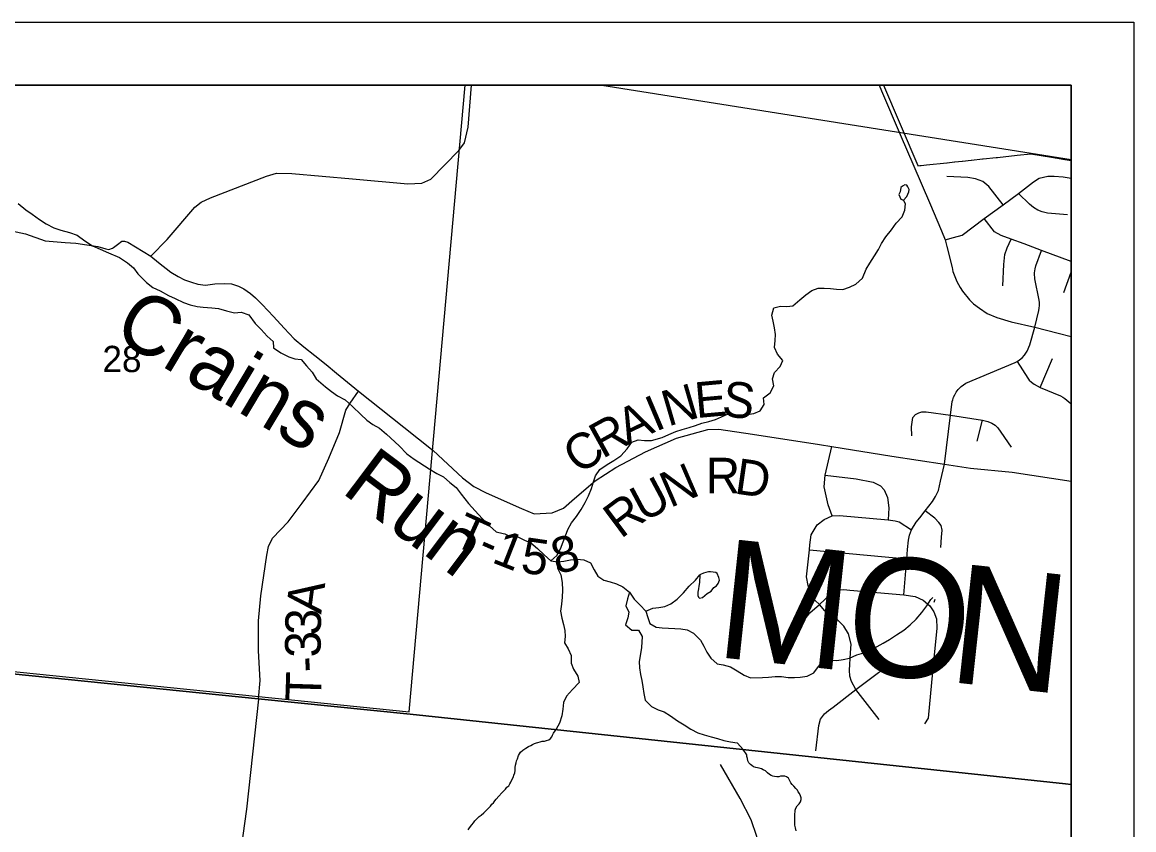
# Model space of a CAD drawing. Extents: x -7.3 to 34, y 0 to 22.
# Drawn here: x 7.229 to 9, y 19.714 to 21 of the extents above; entities that cross this region are included whole.
import ezdxf

# ---------------------------------------------------------------- set-up
doc = ezdxf.new("R2010")
doc.units = 0
for name, color, linetype in [('GM_X_Corporation', 7, 'Continuous'), ('GM_X_County_Road', 7, 'Continuous'), ('GM_X_County_Text', 7, 'Continuous'), ('GM_X_Minor_Lake', 7, 'Continuous'), ('GM_X_Minor_River', 7, 'Continuous'), ('GM_X_Minor_River_Text', 7, 'Continuous'), ('GM_X_Section_Text', 7, 'Continuous'), ('GM_X_Township_Road', 7, 'Continuous'), ('GM_X_Township_Road_Text', 7, 'Continuous'), ('SH_Data', 7, 'Continuous')]:
    doc.layers.add(name, color=color, linetype=linetype)

msp = doc.modelspace()

# ---------------------------------------------------------------- linework, layer by layer
at = {"layer": 'GM_X_Corporation'}
for points in [[(2.7422, 20.0783), (4.2288, 20.048), (4.2328, 20.0479), (4.4762, 20.0428), (4.7954, 20.036), (4.9235, 20.0334), (4.9401, 20.0331), (4.9519, 20.0328), (5.8024, 20.0153), (5.9388, 20.0125), (6.0214, 20.0108), (6.0677, 20.0098), (6.0763, 20.0096), (6.4154, 20.0027), (6.4242, 20.0024), (6.9507, 19.9888), (6.9988, 19.9839), (7.6051, 19.9224), (7.8469, 19.8978), (8.8913, 19.7872), (8.9, 19.7858), (8.9, 20.9), (2.1, 20.9)], [(6.9988, 19.9839), (7.6051, 19.9224), (7.8469, 19.8978), (8.8913, 19.7872), (8.9, 19.7858), (8.9, 20.9), (4.7796, 20.9)], [(8.9, 14.1), (8.9, 19.7858), (8.8913, 19.7872), (7.8469, 19.8978), (7.6051, 19.9224), (6.9988, 19.9839), (6.9507, 19.9888), (6.4242, 20.0024), (6.4154, 20.0027), (6.0763, 20.0096), (6.0677, 20.0098), (6.0214, 20.0108), (5.9388, 20.0125), (5.8024, 20.0153), (4.9519, 20.0328), (4.9401, 20.0331), (4.9235, 20.0334), (4.7954, 20.036), (4.4762, 20.0428), (4.2328, 20.0479), (4.2288, 20.048), (2.7422, 20.0783)], [(8.9, 19.3924), (8.9, 19.7858), (8.8913, 19.7872), (7.8469, 19.8978), (7.6051, 19.9224), (6.9988, 19.9839), (6.9507, 19.9888), (6.4242, 20.0024), (6.4154, 20.0027), (6.0763, 20.0096), (6.0677, 20.0098), (6.0214, 20.0108), (5.9388, 20.0125), (5.8024, 20.0153), (4.9519, 20.0328), (4.9401, 20.0331), (4.9235, 20.0334), (4.7954, 20.036), (4.4762, 20.0428), (4.2328, 20.0479), (4.2288, 20.048), (2.7422, 20.0783)]]:
    msp.add_lwpolyline(points, dxfattribs=at)
for points in [[(7.9348, 20.9), (6.9581, 20.9), (6.9466, 20.8915), (6.9213, 20.878), (6.9137, 20.8592), (6.868, 20.2988), (6.8838, 20.2576), (6.9047, 20.2424), (6.9439, 20.2121), (6.9658, 20.1923), (6.9852, 20.1575), (7.0057, 20.1052), (7.0065, 20.0839), (7.0034, 20.0639), (6.9909, 20.0255), (6.98, 19.9897), (7.8452, 19.9016)], [(8.9, 20.7813), (8.9, 20.9), (8.1523, 20.9)], [(8.9, 20.7798), (8.9, 20.9), (8.6014, 20.9), (8.6559, 20.7719), (8.6561, 20.7713), (8.659, 20.7717), (8.6597, 20.7717), (8.6609, 20.7719), (8.6612, 20.7719), (8.6695, 20.7728), (8.7023, 20.7763), (8.7028, 20.7763), (8.7146, 20.7776), (8.715, 20.7776), (8.7268, 20.7789), (8.7273, 20.7789), (8.7411, 20.7804), (8.7416, 20.7804), (8.7591, 20.7823), (8.7598, 20.7824), (8.7805, 20.7845), (8.7822, 20.7847), (8.783, 20.7848), (8.814, 20.7881), (8.8358, 20.7904), (8.8689, 20.785), (8.8748, 20.784), (8.8754, 20.7839), (8.8902, 20.7815), (8.8908, 20.7814)]]:
    msp.add_lwpolyline(points, close=True, dxfattribs=at)
at = {"layer": 'GM_X_County_Road'}
for points in [[(8.5943, 20.9), (8.5983, 20.8905), (8.6278, 20.8212), (8.6496, 20.7709), (8.6744, 20.7129), (8.6938, 20.668), (8.6997, 20.6534), (8.7022, 20.6428), (8.7104, 20.6092), (8.7117, 20.6029), (8.7183, 20.587), (8.7236, 20.5777)], [(8.7236, 20.5777), (8.727, 20.5718), (8.7385, 20.558), (8.7447, 20.5518), (8.7542, 20.5445), (8.7666, 20.5361), (8.782, 20.5297), (8.8048, 20.523), (8.8421, 20.5142), (8.8794, 20.5048), (8.9, 20.4997)]]:
    msp.add_lwpolyline(points, dxfattribs=at)
at = {"layer": 'GM_X_Minor_Lake'}
for points in [[(8.6332, 20.7167), (8.6382, 20.7227), (8.6418, 20.7298), (8.6423, 20.7336), (8.6401, 20.7378), (8.6386, 20.7405), (8.6352, 20.741), (8.6313, 20.7391), (8.629, 20.7369)], [(8.629, 20.7369), (8.6277, 20.7297), (8.6258, 20.7259), (8.6287, 20.7183), (8.6332, 20.7167)], [(8.3085, 20.12), (8.3083, 20.1077)], [(8.3388, 20.1155), (8.3363, 20.122), (8.334, 20.1239), (8.3298, 20.1244), (8.3257, 20.1248), (8.3222, 20.1245), (8.3184, 20.1235), (8.3142, 20.1228), (8.3096, 20.1206), (8.3085, 20.12)], [(8.3083, 20.1077), (8.307, 20.102), (8.3065, 20.0978), (8.3053, 20.0925), (8.3052, 20.0869), (8.3063, 20.0846), (8.3082, 20.083), (8.3127, 20.0837), (8.3201, 20.0904), (8.3266, 20.0937), (8.3309, 20.0997), (8.3351, 20.1026), (8.3378, 20.106), (8.3399, 20.1117), (8.3388, 20.1155)]]:
    msp.add_lwpolyline(points, dxfattribs=at)
at = {"layer": 'GM_X_Minor_River'}
for points in [[(7.2227, 20.7115), (7.2345, 20.7012), (7.2449, 20.6944), (7.2567, 20.6857), (7.2671, 20.6788), (7.2791, 20.6724), (7.2903, 20.6686), (7.3043, 20.6654), (7.3163, 20.6609), (7.3285, 20.6521), (7.3407, 20.6441), (7.3531, 20.6387), (7.3665, 20.633), (7.3837, 20.6252), (7.3968, 20.6171), (7.4063, 20.6088), (7.4132, 20.5991), (7.4268, 20.5857), (7.4372, 20.5774), (7.4487, 20.5721), (7.4622, 20.5648), (7.4726, 20.5602), (7.4861, 20.5537), (7.4966, 20.5499), (7.5075, 20.5473), (7.5173, 20.5462), (7.531, 20.545), (7.5419, 20.5439), (7.5543, 20.5404), (7.5671, 20.5373), (7.5778, 20.5381), (7.5898, 20.5339), (7.6, 20.5202), (7.6099, 20.5108), (7.6194, 20.4998), (7.629, 20.4915), (7.6294, 20.4813), (7.6409, 20.4737), (7.6536, 20.4672), (7.6633, 20.4642), (7.6735, 20.4631), (7.6819, 20.4529), (7.6907, 20.4427), (7.6972, 20.4323), (7.7119, 20.4192), (7.7215, 20.4117), (7.7315, 20.4049), (7.7435, 20.3988), (7.7553, 20.3878), (7.7685, 20.3752), (7.7781, 20.3665), (7.7877, 20.3593), (7.7981, 20.3533), (7.8096, 20.3442), (7.8294, 20.3253), (7.8419, 20.3127), (7.8534, 20.3039), (7.8771, 20.2887), (7.8894, 20.2815), (7.8999, 20.2758), (7.9102, 20.2671), (7.9205, 20.2588), (7.9282, 20.2482), (7.9402, 20.2338), (7.9504, 20.2217), (7.9618, 20.2095), (7.9735, 20.1981), (7.9842, 20.1882), (7.9951, 20.186), (7.9977, 20.1852)], [(8.0711, 20.1424), (8.0808, 20.1509), (8.0867, 20.1614), (8.0907, 20.1724), (8.0943, 20.1822), (8.0983, 20.192), (8.1042, 20.2029), (8.112, 20.213), (8.1194, 20.2239), (8.1257, 20.2352), (8.1312, 20.2457), (8.136, 20.2574), (8.1389, 20.268), (8.1425, 20.2778), (8.1495, 20.2879), (8.1607, 20.2957), (8.1718, 20.3023), (8.1826, 20.3097), (8.1927, 20.3206), (8.2005, 20.3314), (8.2104, 20.3347), (8.2203, 20.3337), (8.2317, 20.3339), (8.2488, 20.3389), (8.2592, 20.3433), (8.2703, 20.348), (8.2802, 20.3513), (8.2917, 20.3545), (8.3016, 20.3577), (8.3119, 20.3617), (8.323, 20.3642), (8.3333, 20.3674), (8.3429, 20.3718), (8.3536, 20.3761), (8.3642, 20.3752), (8.3741, 20.3746), (8.384, 20.3752), (8.3947, 20.3769), (8.4046, 20.3809), (8.4113, 20.3914), (8.4099, 20.4017), (8.4207, 20.4099), (8.4266, 20.4212), (8.4246, 20.4322), (8.4278, 20.442), (8.4367, 20.4517), (8.4407, 20.4615), (8.4325, 20.4712), (8.4278, 20.4819), (8.4288, 20.4929), (8.4293, 20.5028), (8.4276, 20.5134), (8.4256, 20.5237), (8.4231, 20.5333), (8.4267, 20.5453), (8.437, 20.5478), (8.4473, 20.5473), (8.4568, 20.5486), (8.468, 20.5579), (8.4776, 20.5657), (8.4873, 20.5727), (8.4972, 20.5764), (8.5067, 20.5766), (8.5166, 20.576), (8.5261, 20.5751), (8.5363, 20.5745), (8.547, 20.5781), (8.5573, 20.5829), (8.5678, 20.5925), (8.5734, 20.6065), (8.5796, 20.6163), (8.5871, 20.6279), (8.5933, 20.638), (8.5981, 20.6478), (8.6051, 20.6583), (8.6141, 20.6692), (8.6215, 20.6801), (8.6308, 20.6902), (8.6352, 20.7007), (8.6361, 20.7106), (8.6332, 20.7167)], [(7.9977, 20.1852), (8.0073, 20.1807), (8.0187, 20.1805), (8.0292, 20.1754), (8.0394, 20.1707), (8.0499, 20.1621), (8.0607, 20.152), (8.0711, 20.1424), (8.0817, 20.1406), (8.092, 20.1416), (8.1023, 20.1441), (8.113, 20.145), (8.1236, 20.1437), (8.1345, 20.1389), (8.1404, 20.1278), (8.1459, 20.1178), (8.1556, 20.1116), (8.1655, 20.1087), (8.176, 20.1055), (8.1858, 20.1008), (8.1963, 20.0922), (8.2037, 20.0811), (8.2134, 20.0718), (8.2227, 20.0621), (8.2259, 20.0518), (8.2288, 20.0423), (8.2389, 20.0364), (8.2488, 20.0355), (8.2685, 20.0343), (8.2784, 20.0342), (8.2882, 20.0321), (8.2987, 20.027), (8.3099, 20.0161), (8.3151, 20.0065), (8.3198, 19.997), (8.3261, 19.987), (8.3362, 19.9784), (8.346, 19.9764), (8.3574, 19.9735), (8.3682, 19.9672), (8.3791, 19.9602), (8.3893, 19.9558), (8.4083, 19.9562), (8.4182, 19.9568), (8.4285, 19.9578), (8.4387, 19.958), (8.4493, 19.9566), (8.4592, 19.9565), (8.4687, 19.957), (8.4794, 19.9588), (8.4901, 19.9639), (8.4975, 19.974), (8.5057, 19.9837), (8.5167, 19.9839), (8.527, 19.9837), (8.5372, 19.9851), (8.5472, 19.9875), (8.559, 19.9923), (8.5697, 19.9959), (8.5816, 20.0013), (8.5912, 20.0057), (8.6008, 20.0112), (8.6108, 20.0168), (8.6219, 20.0242), (8.6335, 20.0319), (8.6435, 20.0405), (8.6532, 20.0494), (8.6621, 20.0599), (8.6703, 20.0708), (8.6769, 20.0809), (8.6797, 20.0839)], [(8.0817, 20.1406), (8.0819, 20.1308), (8.087, 20.1197), (8.0895, 20.1075), (8.0896, 20.0957), (8.089, 20.0843), (8.0884, 20.0733), (8.0867, 20.0619), (8.0888, 20.0509), (8.0912, 20.041), (8.0933, 20.0314), (8.0939, 20.0219), (8.093, 20.0117), (8.0989, 20.0021), (8.1036, 19.9917), (8.1037, 19.9792), (8.1074, 19.9697), (8.114, 19.9585), (8.1165, 19.9486), (8.1056, 19.9374), (8.0959, 19.9269), (8.0915, 19.9164), (8.0902, 19.9058), (8.0889, 19.8955), (8.0848, 19.8838), (8.0797, 19.8741)], [(8.2227, 20.0621), (8.2338, 20.0669), (8.2433, 20.0678), (8.2528, 20.0696), (8.2624, 20.074), (8.2724, 20.0814), (8.2825, 20.0914), (8.2918, 20.1019), (8.3015, 20.1116), (8.3085, 20.12)], [(8.1963, 20.0922), (8.1934, 20.0817), (8.1906, 20.0707), (8.1953, 20.0607), (8.194, 20.0513), (8.19, 20.0403), (8.2005, 20.0318), (8.2107, 20.032), (8.2166, 20.0216), (8.2155, 20.0042), (8.2142, 19.9943), (8.212, 19.9818), (8.2122, 19.9716), (8.2139, 19.9613), (8.216, 19.9517), (8.2177, 19.9418), (8.2194, 19.9312), (8.2215, 19.9205), (8.2316, 19.9101), (8.2421, 19.9049), (8.2519, 19.9017), (8.2621, 19.8955), (8.2729, 19.8873), (8.2838, 19.881), (8.2943, 19.8744), (8.3052, 19.8681), (8.3154, 19.8652), (8.3267, 19.862), (8.3369, 19.8592), (8.3468, 19.8563), (8.3577, 19.8538), (8.368, 19.8525), (8.3781, 19.8414)], [(8.6819, 20.0762), (8.6836, 20.0814)], [(7.9882, 19.7674), (7.9929, 19.7726), (7.996, 19.7752), (7.9987, 19.7786), (8.001, 19.7819), (8.0041, 19.7838), (8.0061, 19.7871), (8.0076, 19.7898), (8.0096, 19.7943), (8.0116, 19.798), (8.0124, 19.8007), (8.0137, 19.8044), (8.0141, 19.8086), (8.0146, 19.8132), (8.0151, 19.8166), (8.0159, 19.8204), (8.0164, 19.8238), (8.0179, 19.8268), (8.0196, 19.8324), (8.0231, 19.8373), (8.0266, 19.8406), (8.0312, 19.844), (8.0354, 19.8465), (8.0393, 19.8483), (8.042, 19.8498), (8.0454, 19.8513), (8.0481, 19.8523), (8.0507, 19.853), (8.0542, 19.8541), (8.0576, 19.8548), (8.061, 19.8551), (8.0645, 19.8562), (8.0679, 19.8572), (8.0706, 19.8594), (8.0726, 19.8621), (8.0738, 19.8647), (8.0753, 19.8677), (8.0781, 19.8714), (8.0797, 19.8741)], [(8.4247, 19.7993), (8.4221, 19.8005), (8.4194, 19.8021), (8.4165, 19.8048), (8.4131, 19.8076), (8.4094, 19.8096), (8.4067, 19.8108), (8.4033, 19.812), (8.4003, 19.8128), (8.3977, 19.8132), (8.3943, 19.8144), (8.3917, 19.8164), (8.3891, 19.818), (8.3865, 19.8203), (8.385, 19.8238), (8.3843, 19.8272), (8.3837, 19.8306), (8.3833, 19.8333), (8.3778, 19.8417)], [(8.4619, 19.7123), (8.4608, 19.7169), (8.4602, 19.7215), (8.4599, 19.7245), (8.4599, 19.7283), (8.46, 19.7325), (8.4597, 19.7359), (8.4602, 19.7393), (8.4603, 19.7427), (8.4607, 19.7454), (8.4615, 19.7484), (8.4639, 19.7518), (8.4666, 19.7551), (8.4689, 19.7585), (8.4698, 19.7619), (8.4702, 19.7646), (8.4691, 19.768), (8.4673, 19.7715), (8.4655, 19.7745), (8.4644, 19.7772), (8.4614, 19.7799), (8.4581, 19.7834), (8.4555, 19.7861), (8.4537, 19.7888), (8.4515, 19.7927), (8.4497, 19.7961), (8.4467, 19.7981), (8.444, 19.7993), (8.4406, 19.7994), (8.4372, 19.7991), (8.4345, 19.7984), (8.4311, 19.7984), (8.4273, 19.7989), (8.4247, 19.7993)], [(7.9396, 19.7137), (7.9416, 19.7171), (7.9455, 19.7216), (7.9478, 19.725), (7.9502, 19.7283), (7.9525, 19.7309), (7.9572, 19.735), (7.9602, 19.7372), (7.9645, 19.7409), (7.9672, 19.7435), (7.9703, 19.7465), (7.9753, 19.7517), (7.9773, 19.7547), (7.98, 19.7569), (7.982, 19.7599), (7.9839, 19.7625), (7.9882, 19.7674)]]:
    msp.add_lwpolyline(points, dxfattribs=at)
at = {"layer": 'GM_X_Township_Road'}
for p, q in [((8.8886, 20.5694), (8.9, 20.6018)), ((8.8508, 20.4185), (8.8705, 20.4647)), ((8.7503, 20.3328), (8.7592, 20.3662)), ((8.4831, 20.1597), (8.6383, 20.1454))]:
    msp.add_line(p, q, dxfattribs=at)
for points in [[(7.4336, 20.6277), (7.4598, 20.6539), (7.5039, 20.7056), (7.5139, 20.7134), (7.5288, 20.7204), (7.6183, 20.7549), (7.6339, 20.7596), (7.6586, 20.7589), (7.7549, 20.7506), (7.8435, 20.7427), (7.8658, 20.7435), (7.8798, 20.7503), (7.9245, 20.7957), (7.9338, 20.8079), (7.9395, 20.8329), (7.945, 20.9)], [(8.6997, 20.6534), (8.713, 20.6572), (8.7266, 20.6611), (8.7614, 20.6873), (8.7917, 20.709), (8.8161, 20.7275), (8.8404, 20.7461), (8.8495, 20.7516), (8.8629, 20.7547), (8.8733, 20.755), (8.8877, 20.754), (8.9, 20.7517)], [(8.7917, 20.709), (8.769, 20.7386), (8.7593, 20.7463), (8.748, 20.7505), (8.7355, 20.7529), (8.702, 20.7544)], [(8.8943, 20.6934), (8.8624, 20.6957), (8.8543, 20.6978), (8.847, 20.7006), (8.8405, 20.7047), (8.8338, 20.7102), (8.8161, 20.7275)], [(7.1337, 20.6869), (7.1706, 20.6775), (7.2044, 20.6696), (7.2341, 20.6632), (7.2654, 20.6518), (7.2976, 20.6492), (7.3146, 20.6481), (7.3494, 20.6426), (7.362, 20.6389), (7.3671, 20.6383), (7.3727, 20.6404), (7.3743, 20.6415)], [(8.9, 20.6192), (8.8531, 20.6363), (8.8251, 20.647), (8.8044, 20.6546), (8.7886, 20.6604), (8.7779, 20.6662), (8.7614, 20.6873)], [(7.3743, 20.6415), (7.3808, 20.6461), (7.3877, 20.6512), (7.3921, 20.6513), (7.3973, 20.6498), (7.4336, 20.6277), (7.4463, 20.6172), (7.4658, 20.6019), (7.4774, 20.5949), (7.4876, 20.59), (7.4985, 20.5858), (7.5089, 20.5826), (7.5207, 20.5815), (7.536, 20.5832), (7.5519, 20.5839), (7.5626, 20.5832), (7.5733, 20.5799), (7.5822, 20.5755), (7.5925, 20.5681), (7.6006, 20.5612), (7.6111, 20.5505), (7.6293, 20.5313), (7.6463, 20.5128), (7.6622, 20.496), (7.6776, 20.4832), (7.6952, 20.4693), (7.7133, 20.4547), (7.7296, 20.4413), (7.7649, 20.4125), (7.8367, 20.3552), (7.8837, 20.3178), (7.9304, 20.2743), (7.9483, 20.2605), (7.9684, 20.2507), (8.0246, 20.2257), (8.0446, 20.2173), (8.0731, 20.2187), (8.0911, 20.226), (8.1088, 20.2416), (8.1416, 20.2699), (8.175, 20.291), (8.2222, 20.316), (8.2715, 20.3375), (8.3211, 20.3515), (8.3386, 20.3519), (8.3927, 20.3438), (8.4991, 20.3275), (8.5187, 20.3243), (8.6145, 20.3088), (8.6986, 20.2962), (8.7401, 20.29), (8.8061, 20.2833), (8.9, 20.2693)], [(8.7912, 20.5802), (8.7932, 20.6143), (8.7946, 20.6301), (8.7981, 20.6408), (8.8044, 20.6546)], [(8.6338, 20.0879), (8.6383, 20.1454), (8.6395, 20.1604), (8.6412, 20.1751), (8.6425, 20.1831), (8.6457, 20.1916), (8.6535, 20.2039), (8.6592, 20.2109), (8.6676, 20.2219), (8.6793, 20.237), (8.6843, 20.2447), (8.6891, 20.2543), (8.6921, 20.2693), (8.6986, 20.2962), (8.7082, 20.3742), (8.7109, 20.3959), (8.7116, 20.3989), (8.7129, 20.4028), (8.7147, 20.4065), (8.7171, 20.4111), (8.7202, 20.4152), (8.7249, 20.42), (8.7322, 20.425), (8.8109, 20.4582), (8.8141, 20.4599), (8.818, 20.4625), (8.8222, 20.4656), (8.8261, 20.4696), (8.8302, 20.4761), (8.8342, 20.4864), (8.8421, 20.5142), (8.8487, 20.5408), (8.8495, 20.5449), (8.8499, 20.5491), (8.8497, 20.5537), (8.8491, 20.5575), (8.8425, 20.5913), (8.8421, 20.5941), (8.8418, 20.5972), (8.8419, 20.601), (8.8422, 20.6041), (8.8428, 20.6074), (8.8442, 20.6119), (8.8531, 20.6363)], [(8.8141, 20.4599), (8.8311, 20.4329), (8.8335, 20.4301), (8.8369, 20.4268), (8.8412, 20.4234), (8.8508, 20.4185), (8.8831, 20.4048), (8.887, 20.4027), (8.8903, 20.4006), (8.8936, 20.3983), (8.8966, 20.3957), (8.9, 20.3924)], [(7.6053, 19.9219), (7.6078, 19.9516), (7.6056, 19.9991), (7.6056, 20.0465), (7.6091, 20.0867), (7.6188, 20.1513), (7.6213, 20.1652), (7.6279, 20.1784), (7.6528, 20.2044), (7.6749, 20.2342), (7.7015, 20.2703), (7.7172, 20.3057), (7.7347, 20.3465), (7.7445, 20.3821), (7.7515, 20.3931), (7.7649, 20.4125)], [(8.6463, 20.3412), (8.6459, 20.3556), (8.6482, 20.3705), (8.6524, 20.3752), (8.6575, 20.3777), (8.6625, 20.3794), (8.6694, 20.3793), (8.7082, 20.3742)], [(8.7082, 20.3742), (8.7592, 20.3662), (8.7675, 20.3641), (8.7739, 20.3615), (8.7791, 20.3584), (8.7835, 20.3538), (8.7882, 20.3469), (8.8049, 20.3233)], [(8.5195, 20.2138), (8.5131, 20.2315), (8.5067, 20.2601), (8.5084, 20.2788), (8.5187, 20.3243)], [(8.5084, 20.2788), (8.5575, 20.2726), (8.5846, 20.2677), (8.5963, 20.2618), (8.6021, 20.2551), (8.6077, 20.2431), (8.6099, 20.2268), (8.6086, 20.2073)], [(8.5941, 19.8898), (8.557, 19.9376), (8.5501, 19.9499), (8.5476, 19.9586), (8.5468, 19.968), (8.5484, 19.9959), (8.5496, 20.0095), (8.5456, 20.0259), (8.5382, 20.0383), (8.5274, 20.0488), (8.5077, 20.0628), (8.499, 20.0727), (8.4925, 20.0792), (8.4855, 20.0902), (8.4811, 20.1028), (8.4785, 20.1169), (8.4831, 20.1597), (8.4837, 20.1675), (8.486, 20.1838), (8.4958, 20.1997), (8.5068, 20.2083), (8.5195, 20.2138), (8.5309, 20.2143), (8.6086, 20.2073), (8.6199, 20.2062), (8.6262, 20.2044), (8.6457, 20.1916)], [(8.6927, 20.1637), (8.6934, 20.1799), (8.6945, 20.1909), (8.6932, 20.1984), (8.6896, 20.2034), (8.6832, 20.2103), (8.6676, 20.2219)], [(8.499, 20.0727), (8.5169, 20.0891), (8.5242, 20.0933), (8.5303, 20.0958), (8.5378, 20.0964), (8.5475, 20.0957), (8.6338, 20.0879), (8.6516, 20.0855), (8.6644, 20.0798), (8.6751, 20.0705), (8.6812, 20.0608), (8.6859, 20.0498), (8.6863, 20.0352), (8.6794, 19.9655), (8.6725, 19.8919), (8.6668, 19.8828)], [(8.4725, 20.0449), (8.4841, 20.0594), (8.499, 20.0727)], [(8.4936, 19.8395), (8.498, 19.8799), (8.5007, 19.89), (8.507, 19.8984), (8.5138, 19.904), (8.5208, 19.9093), (8.557, 19.9376), (8.5932, 19.9642), (8.5992, 19.9674), (8.6054, 19.9697), (8.6127, 19.9708), (8.6206, 19.9711), (8.6794, 19.9655)], [(7.6053, 19.9219), (7.5861, 19.7466), (7.5695, 19.6248), (7.5594, 19.5121), (7.5576, 19.494), (7.5493, 19.4144), (7.5434, 19.3715)], [(8.3085, 19.3272), (8.3108, 19.3535), (8.3105, 19.3714), (8.3105, 19.385), (8.3326, 19.571), (8.3362, 19.5774), (8.3575, 19.5826), (8.395, 19.5951), (8.404, 19.6085), (8.4044, 19.6378), (8.3994, 19.7032), (8.3902, 19.73), (8.3728, 19.7638), (8.3414, 19.8181)]]:
    msp.add_lwpolyline(points, dxfattribs=at)
at = {"layer": 'SH_Data'}
for p, q in [((2, 21), (9, 21)), ((9, 21), (9, 14)), ((2.1, 20.9), (8.9, 20.9)), ((8.9, 20.9), (8.9, 14.1))]:
    msp.add_line(p, q, dxfattribs=at)

# ---------------------------------------------------------------- texts
at = {"layer": 'GM_X_County_Text'}
for s, rotation, p in [('M', 353.897, (8.3302, 19.9896)), ('O', 353.8904, (8.5348, 19.9677)), ('N', 353.7667, (8.7013, 19.9499))]:
    msp.add_text(s, height=0.1894, rotation=rotation, dxfattribs=at).set_placement(p)
at = {"layer": 'GM_X_Minor_River_Text'}
for s, height, rotation, p in [('Crains', 0.09469, 329.1185, (7.3701, 20.5006)), ('Run', 0.09468, 323.0459, (7.7355, 20.2523))]:
    msp.add_text(s, height=height, rotation=rotation, dxfattribs=at).set_placement(p)
at = {"layer": 'GM_X_Section_Text'}
msp.add_text('28', height=0.04186, rotation=0, dxfattribs=at).set_placement((7.3567, 20.4428))
at = {"layer": 'GM_X_Township_Road_Text'}
for s, rotation, p in [('N', 16.2907, (8.2579, 20.356)), ('E', 5.2078, (8.303, 20.3695)), ('S', 352.8231, (8.3421, 20.3734)), ('I', 22.9531, (8.238, 20.3475)), ('A', 25.4784, (8.1935, 20.3263)), ('R', 28.8435, (8.1534, 20.3042)), ('C', 35.0563, (8.1166, 20.2782)), ('N', 23.3851, (8.2612, 20.2261)), ('R', 359.9473, (8.3179, 20.2496)), ('D', 351.7738, (8.3624, 20.2497)), ('U', 28.1015, (8.2182, 20.2031)), ('R', 36.7028, (8.1827, 20.1764)), ('T', 335.6108, (7.9122, 20.1688)), ('-', 336.1671, (7.9514, 20.151)), ('1', 338.5727, (7.9752, 20.1405)), ('5', 351.7293, (8.0215, 20.1241)), ('8', 14.3773, (8.0804, 20.1204)), ('A', 82.5368, (7.7053, 20.0565)), ('3', 87.944, (7.7042, 20.0229)), ('3', 91.1501, (7.7049, 19.9888)), ('-', 93.1409, (7.7061, 19.966)), ('T', 88.1911, (7.7049, 19.9182))]:
    msp.add_text(s, height=0.0568, rotation=rotation, dxfattribs=at).set_placement(p)

doc.saveas('drawing.dxf')
